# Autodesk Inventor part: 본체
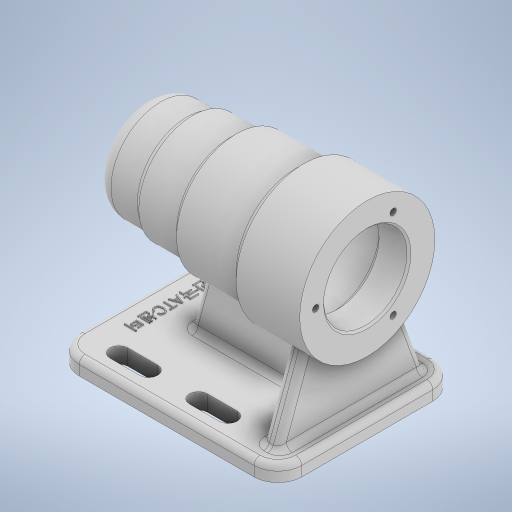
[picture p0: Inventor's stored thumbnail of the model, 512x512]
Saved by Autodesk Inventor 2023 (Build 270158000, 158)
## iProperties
Created: 2022-07
Part Number: 본체
Material: 일반
Document SubType Name: Modeling
Designer: owner
Density: 1 g/cm^3
Appearance: 기본값
Author: owner
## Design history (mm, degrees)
sketch "스케치1"
  geometry: L1 (56, -45)-(-56, -45); L2 (-56, -45)-(-56, 45); L3 (-56, 45)-(56, 45); L4 (56, 45)-(56, -45); 1 further point
  constraints: 8 end point, 2 parallel, 1 horizontal, 1 perpendicular
  dimensions: "d0" = 112 distance of L1.start L1.end; "d1" = 90 distance of L3.end L1.start; "d2" = 45 distance from line of point (0, 0) L1; "d3" = 56 distance from line of point (0, 0) L2
extrude "돌출1" new body sketch "스케치1" distance "d4" = 8; taper "d5" = 0 deg
sketch "스케치2"
  geometry: L1 (-36, -33)-(-21, -33); L2 (-36, -37.5)-(-21, -37.5); L3 (-21, -28.5)-(-36, -28.5); L4 (-56, 45)-(-56, -45) reference; L5 (4, -33)-(19, -33); L6 (4, -37.5)-(19, -37.5); L7 (19, -28.5)-(4, -28.5); A1 r 4.5 centre (-36, -33) between (-36, -28.5) and (-36, -37.5); A2 r 4.5 centre (-21, -33) between (-21, -37.5) and (-21, -28.5); A3 r 4.5 centre (4, -33) between (4, -28.5) and (4, -37.5); A4 r 4.5 centre (19, -33) between (19, -37.5) and (19, -28.5); 4 further points
  constraints: 16 end point, 8 point on circle, 8 tangent, 4 centre point, 3 midpoint, 2 horizontal, 2 parallel
  dimensions: "d6" = 15 distance of L1.start L1.end; "d7" = 20 distance from line of L4 L1.start; "d8" = 9 distance from line of L2 point (-28.5, -28.5); "d9" = 33 vertical distance of point (-28.5, -33) point (0, 0); "d10" = 25 distance of L5.start L1.end; "d11" = 15 distance of L5.start L5.end; "d12" = 9 distance between parallel lines of L6 L7; "d13" = 33 distance from line of L5 point (0, 0)
extrude "돌출2" cut sketch "스케치2" distance "d14" = 8; taper "d15" = 0 deg
fillet "모깎기1" dims "d16" = 12
sketch "스케치3"
  geometry: L1 (-56, 70)-(56, 70); L2 (-44, 0)-(44, 0) reference; L3 (-56, 70)-(-56, 87); L4 (-48, 95)-(-32, 95); L5 (-32, 95)-(-32, 97); L6 (-32, 97)-(-10, 97); L7 (-10, 97)-(-10, 100); L8 (-10, 100)-(24, 100); L9 (24, 100)-(24, 104); L10 (24, 104)-(56, 104); L11 (56, 104)-(56, 92); L12 (55, 91)-(41, 91); L13 (41, 91)-(41, 91); L14 (38, 94)-(-10, 94); L15 (-13, 91)-(-13, 91); L16 (-13, 91)-(-24.7, 91); L17 (-25, 90.7)-(-25, 87.5); L18 (-25, 87.5)-(-42.7, 87.5); L19 (-43, 87.2)-(-43, 86); L20 (-43, 86)-(-46.7, 86); L21 (-47, 85.7)-(-47, 80.5); L22 (-47, 80.5)-(-47, 80.5); L23 (-50, 77.5)-(-50, 70); L24 (55, 91)-(56, 92); A1 r 0.3 centre (-46.7, 85.7) between (-46.7, 86) and (-47, 85.7); A2 r 0.3 centre (-42.7, 87.2) between (-42.7, 87.5) and (-43, 87.2); A3 r 0.3 centre (-24.7, 90.7) between (-24.7, 91) and (-25, 90.7); A4 r 8 centre (-48, 87) between (-48, 95) and (-56, 87); A5 r 3 centre (-47, 77.5) between (-47, 80.5) and (-50, 77.5); A6 r 3 centre (-10, 91) between (-10, 94) and (-13, 91); A7 r 3 centre (38, 91) between (41, 91) and (38, 94); 16 further points
  constraints: 46 end point, 18 perpendicular, 17 point on line, 14 point on circle, 14 tangent, 7 centre point, 4 equal radius, 3 midpoint, 2 horizontal, 2 vertical, 2 vertical alignment
  dimensions: "d17" = 112 distance of L1.start L1.end; "d18" = 70 distance between parallel lines of L2 L1; "d19" = 68 diameter of L10 L1; "d20" = 50 diameter of L4 L1; "d21" = 54 diameter of L6 L1; "d22" = 60 diameter of L8 L1; "d23" = 42 diameter of L12 L1; "d24" = 48 diameter of L14 L1; "d25" = 42 diameter of L16 L1; "d26" = 35 diameter of L18 L1; "d27" = 32 diameter of L20 L1; "d28" = 21 diameter of L22 L1; "d29" = 15 distance of point (56, 91) L12.end; "d30" = 54 distance of point (41, 94) point (-13, 94); "d31" = 12 distance of L15.end point (-25, 91); "d32" = 18 distance of L17.end point (-43, 87.5); "d33" = 24 distance of point (-56, 95) L4.end; "d34" = 46 distance from line of point (-10, 98.5) L3; "d35" = 80 distance from line of L3 point (24, 102); "d36" = 3 distance of L21.end point (-50, 80.5); "d37" = 4 distance of L19.end point (-47, 86); "d38" = 0.3 radius of A1; "d39" = 8 radius of A4; "d40" = 3 radius of A5; "d41" = 1 distance of L12.start point (56, 91); "d42" = 1 distance of L11.end point (56, 91) (= d41)
revolve "회전1" sketch "스케치3" stored, may be unused: angle "d43" = 90 deg
fillet "모깎기2" dims "d44" = 3
fillet "모깎기3" dims "d45" = 4
node "작업 평면1"
sketch "스케치4"
  geometry: L1 (66, 8)-(0, 8) reference; L2 (-4, 8)-(11.103, 49.494); L3 (54.897, 49.494)-(70, 8); L4 (-12, 8)-(-12, 0) reference; L5 (78, 0)-(78, 8) reference; L6 (-4, 8)-(70, 8); L7 (66, 8)-(78, 8) reference; A1 r 30 centre (33, 70) between (11.103, 49.494) and (54.897, 49.494); 7 further points
  constraints: 6 end point, 2 point on circle, 2 point on line, 1 centre point, 1 coincident, 1 collinear, 1 midpoint, 5 other
  dimensions: "d47" = 110 deg angle of L1 L2; "d48" = 110 deg angle of L1 L3; "d49" = 8 horizontal distance of point (-12, 4) L2.start; "d50" = 8 distance from line of L5 L3.end
extrude "돌출3" join sketch "스케치4" distance "d51" = 8; taper "d52" = 0 deg
sketch "스케치5"
  geometry: L1 (-44, 8)-(44, 8) reference; L2 (-29, 8)-(-19.27, 44.313); 2 further points
  constraints: 2 end point, 1 point on line
  dimensions: "d53" = 105 deg angle of L1 L2; "d54" = 77 distance of point (48, 8) L2.start; "d55" = 36.31285 vertical distance of L2.start L2.end
feature "리브1" sketch "스케치5" dims "d56" = 1, "d57" = 8, "d58" = 0, "d59" = 0, "d60" = 1, "d61" = 1
fillet "모깎기4" dims "d62" = 3
fillet "모깎기5" dims "d63" = 3
sketch "스케치7"
  geometry: C1 r 34 at (0, 0) reference; 2 further points
  constraints: 1 horizontal alignment
  dimensions: "d72" = 26 distance of C1.centre point (-26, 0)
hole "구멍2" sketch "스케치7" at (-26, 0) diameter "d73" = 3.242; stored, may be unused: countersink angle "d77" = 90 deg, drill point angle "d79" = 118 deg; dims "d74" = 8, "d75" = 4, "d76" = 2, "d78" = 11
sketch "스케치8"
  geometry: L1 (-56, 33)-(-56, -33) reference; 2 further points
  constraints: 1 horizontal alignment, 1 other
  dimensions: "d83" = 12 distance from line of L1 point (-44, 0)
feature "엠보싱1" sketch "스케치8" dims "d0" = 112, "d1" = 90, "d2" = 45, "d3" = 56, "d13" = 33, "d84" = 0.5, "d85" = 0
node "솔리드1"
mirror "미러1"
pattern_circular "원형 패턴1" dims angle "d81" = 360 deg
feature "A9D066F2-1C7D-4E18-AEED-F7BC21143FA4" dims "d73" = 3.242, "d74" = 8, "d75" = 4, "d76" = 2, "d77" = 90 deg, "d78" = 11, "d79" = 118 deg
other parameters: "d46" = -8
